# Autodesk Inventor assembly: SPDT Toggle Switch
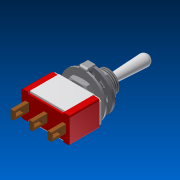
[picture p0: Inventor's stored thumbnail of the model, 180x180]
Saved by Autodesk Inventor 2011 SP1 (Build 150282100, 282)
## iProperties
Created: 2011-11
Part Number: SPDT Toggle Switch
Document SubType Name: Assembly
Designer: sdarley
Author: sdarley
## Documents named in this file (8)
- C:\Users\sdarley\Documents\Inventor\General Design Work\SPDT Toggle Switch\SPDT Toggle Switch.iam
- C:\Users\sdarley\Documents\Inventor\General Design Work\SPDT Toggle Switch\Components\SPDT Toggle Switch Base.ipt
- C:\Users\sdarley\Documents\Inventor\General Design Work\SPDT Toggle Switch\Components\SPDT Toggle Switch Pin.ipt
- C:\Users\sdarley\Documents\Inventor\General Design Work\SPDT Toggle Switch\Components\SPDT Toggle Switch Treaded Tube.ipt
- C:\Users\sdarley\Documents\Inventor\General Design Work\SPDT Toggle Switch\Components\Toggle Switch.ipt
- C:\Users\sdarley\Documents\Inventor\General Design Work\SPDT Toggle Switch\Components\M6x0.5 Hex Nut.ipt
- C:\Users\sdarley\Documents\Inventor\General Design Work\SPDT Toggle Switch\Components\SPDT Toggle Switch Anti-Rotation Washer.ipt
- C:\Users\sdarley\Documents\Inventor\Content Center Files\R2011\en-US\AS 1969(2)\AS 1969 - M6(2).ipt
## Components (10 placed, 7 different names)
1. SPDT Toggle Switch Base:1 — Flush:1, Flush:2, Mate:1, Mate:2, Flush:3, Flush:4, Flush:5, Flush:6, Flush:7, Flush:8
2. SPDT Toggle Switch Pin:1 — Flush:1, Flush:2
3. SPDT Toggle Switch Pin:2 — Mate:2, Flush:5, Flush:6
4. SPDT Toggle Switch Pin:3 — Mate:1, Flush:3, Flush:4
5. SPDT Toggle Switch Treaded Tube:1 — Flush:7, Flush:8, Mate:3, Mate:4, Insert:1, Mate:2, Mate:6
6. Toggle Switch:1 — Mate:3, Mate:4
7. M6x0.5 Hex Nut:1 — Insert:1, Flush:9
8. M6x0.5 Hex Nut:2 — Mate:6, Mate:7
9. SPDT Toggle Switch Anti-Rotation Washer:1 — Flush:9, Mate:5
10. AS 1969 (Internal Tooth Lock Washer Type A) M6:1 — Mate:2, Mate:5, Mate:7
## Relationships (18: Flush 9, Mate 8, Insert 1)
- Flush:1: SPDT Toggle Switch Base:1 ↔ SPDT Toggle Switch Pin:1
- Flush:2: SPDT Toggle Switch Base:1 ↔ SPDT Toggle Switch Pin:1
- Mate:1: SPDT Toggle Switch Base:1 ↔ SPDT Toggle Switch Pin:3
- Mate:2: SPDT Toggle Switch Base:1 ↔ SPDT Toggle Switch Pin:2
- Flush:3: SPDT Toggle Switch Base:1 ↔ SPDT Toggle Switch Pin:3
- Flush:4: SPDT Toggle Switch Base:1 ↔ SPDT Toggle Switch Pin:3
- Flush:5: SPDT Toggle Switch Base:1 ↔ SPDT Toggle Switch Pin:2
- Flush:6: SPDT Toggle Switch Base:1 ↔ SPDT Toggle Switch Pin:2
- Flush:7: SPDT Toggle Switch Base:1 ↔ SPDT Toggle Switch Treaded Tube:1
- Flush:8: SPDT Toggle Switch Base:1 ↔ SPDT Toggle Switch Treaded Tube:1
- Mate:3: SPDT Toggle Switch Treaded Tube:1 ↔ Toggle Switch:1
- Mate:4: SPDT Toggle Switch Treaded Tube:1 ↔ Toggle Switch:1
- Insert:1: SPDT Toggle Switch Treaded Tube:1 ↔ M6x0.5 Hex Nut:1
- Flush:9: M6x0.5 Hex Nut:1 ↔ SPDT Toggle Switch Anti-Rotation Washer:1
- Mate:2: SPDT Toggle Switch Treaded Tube:1 ↔ AS 1969 (Internal Tooth Lock Washer Type A) M6:1
- Mate:5: SPDT Toggle Switch Anti-Rotation Washer:1 ↔ AS 1969 (Internal Tooth Lock Washer Type A) M6:1
- Mate:6: SPDT Toggle Switch Treaded Tube:1 ↔ M6x0.5 Hex Nut:2
- Mate:7: M6x0.5 Hex Nut:2 ↔ AS 1969 (Internal Tooth Lock Washer Type A) M6:1
